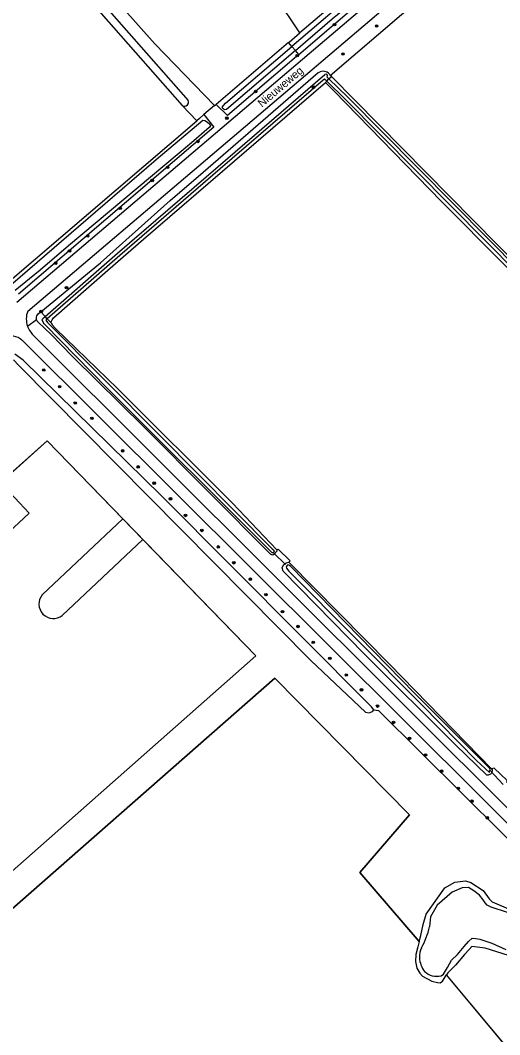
# Model space of a CAD drawing. Extents: x 141000 to 143000, y 400580 to 403500.
# Drawn here: x 141460.4 to 141610, y 402328.5 to 402645.4 of the extents above; entities that cross this region are included whole.
import ezdxf

# ---------------------------------------------------------------- set-up
doc = ezdxf.new("R2010")
doc.units = 0
for name, color, linetype in [('gg-afsc-hekwerk', 7, 'Continuous'), ('gg-anno-openbare ruimte label', 7, 'Continuous'), ('gg-knt-bronhoudergrens', 7, 'Continuous'), ('gg-knt-verharding', 7, 'Continuous'), ('gg-kntw-bovenkant insteek waterloop', 7, 'Continuous'), ('gg-kntw-waterlijn', 7, 'Continuous'), ('gg-kwrk-duiker nz buis', 7, 'Continuous'), ('gt-grn-groengrens', 7, 'Continuous'), ('gt-grn-vlakafsluiter', 7, 'Continuous'), ('gt-symb-boom', 7, 'Continuous'), ('gx-grn-maaiveld', 7, 'Continuous')]:
    doc.layers.add(name, color=color, linetype=linetype)

# ---------------------------------------------------------------- blocks, each defined once
blk = doc.blocks.new('gt0-BOOM')
at = {"layer": 'gt-symb-boom'}
for radius in [0.4, 0.2]:
    blk.add_circle((0, 0), radius, dxfattribs=at)

msp = doc.modelspace()

# ---------------------------------------------------------------- linework, layer by layer
at = {"layer": 'gg-afsc-hekwerk'}
msp.add_line((141619.05, 402316.54), (141593.45, 402347.23), dxfattribs=at)
for points in [[(141391.61, 402482.73), (141409.84, 402461.09), (141468.74, 402514.04), (141533.84, 402446.84), (141434.41, 402358.97)], [(141584.92, 402357.7), (141566.39, 402379.2), (141581.84, 402397.23), (141539.83, 402439.9), (141439.73, 402351.99)]]:
    msp.add_lwpolyline(points, dxfattribs=at)
at = {"layer": 'gg-knt-bronhoudergrens'}
for p, q in [((141510.9, 402618.77), (141515.42, 402614.02)), ((141467.21, 402465.95), (141492.38, 402489.64)), ((141498.64, 402483.18), (141473.47, 402459.49))]:
    msp.add_line(p, q, dxfattribs=at)
for points in [[(141521.02, 402618.74), (141502.4, 402638.08), (141487.01, 402655.3), (141427.04, 402727.42)], [(141557.11, 402628.18), (141608.82, 402672.5), (141656.05, 402713.39)], [(141492.38, 402489.64), (141468.74, 402514.04), (141454.22, 402500.98)], [(141454.22, 402500.98), (141463.12, 402491.43), (141413.75, 402445.4), (141384.54, 402476.72)], [(141434.41, 402358.97), (141533.84, 402446.84), (141498.64, 402483.18)], [(141540.42, 402480.02), (141540.91, 402480.22), (141544.58, 402476.53), (141544.15, 402476.12)], [(141439.73, 402351.99), (141539.83, 402439.9), (141581.84, 402397.23), (141566.39, 402379.2), (141584.92, 402357.7)], [(141612.29, 402407.3), (141612.31, 402407.96), (141608.33, 402411.82), (141607.45, 402411.59)], [(141619.64, 402315.72), (141619.64, 402315.83), (141619.05, 402316.54), (141593.45, 402347.23)]]:
    msp.add_lwpolyline(points, dxfattribs=at)
msp.add_arc((141470.69, 402463.06), 4.52, 140.2654, 307.915, dxfattribs=at)
at = {"layer": 'gg-knt-verharding'}
for p, q in [((141462.66, 402554.52), (141652.94, 402716.56)), ((141670.23, 402341.6), (141464.11, 402547.4))]:
    msp.add_line(p, q, dxfattribs=at)
for points in [[(141459.24, 402557.32), (141548.5, 402633.27), (141649.58, 402719.27), (141645.3, 402724.86)], [(141460.89, 402545.45), (141652.48, 402354.64), (141667.93, 402339.26)]]:
    msp.add_lwpolyline(points, dxfattribs=at)
for centre, radius, start, end in [((141469.02, 402552.11), 6.8, 159.2203, 199.7829), ((141469.02, 402552.11), 6.81, 199.8205, 223.8083), ((141457.83, 402542.37), 4.34, 45.2233, 122.9976)]:
    msp.add_arc(centre, radius, start, end, dxfattribs=at)
at = {"layer": 'gg-kntw-bovenkant insteek waterloop'}
for p, q in [((141564, 402655.43), (141547.64, 402641.46)), ((141544.27, 402638.59), (141547.64, 402641.46)), ((141544.12, 402638.46), (141521.47, 402619.12)), ((141557.47, 402627.82), (141557.11, 402628.18)), ((141456.44, 402563.52), (141515.42, 402614.02))]:
    msp.add_line(p, q, dxfattribs=at)
for points in [[(141417.72, 402724.06), (141436, 402703.38), (141474.9, 402659.83), (141510.9, 402618.77)], [(141422.62, 402725.57), (141421.61, 402724.68), (141421.48, 402724.13), (141421.62, 402723.85), (141512.74, 402620.3)], [(141547.27, 402634.72), (141647.53, 402720.58), (141644.78, 402724.41)], [(141547.27, 402634.72), (141525.06, 402615.7), (141521.47, 402619.12)], [(141466.75, 402554.32), (141485.36, 402569.62), (141507.17, 402589.13), (141517.47, 402597.91), (141553.38, 402629.06), (141553.98, 402629.29)], [(141470.06, 402550.74), (141470.01, 402551.16), (141470.33, 402551.86), (141470.76, 402552.41), (141487.67, 402567.37), (141498.78, 402577.04), (141555.61, 402625.98)], [(141555.61, 402625.98), (141558.2, 402623.41), (141591.86, 402588.8), (141630.63, 402549.74), (141682.01, 402497.77), (141754.99, 402423.77)], [(141557.47, 402627.82), (141609.16, 402575.48), (141658.72, 402525.06), (141659.52, 402524.25), (141660.27, 402523.5)], [(141517.67, 402615.95), (141520.77, 402612.04), (141459.83, 402559.88)], [(141517.67, 402615.95), (141516.27, 402614.75), (141515.42, 402614.02)], [(141465.37, 402551.97), (141465.37, 402552.69), (141465.56, 402553.1), (141466.07, 402553.76), (141466.75, 402554.32)], [(141540.42, 402480.02), (141540.42, 402479.53), (141539.6, 402478.61), (141539.18, 402478.34), (141538.62, 402478.57), (141519.08, 402498.08), (141498.98, 402518.33), (141476.76, 402540.31), (141469.79, 402547.41), (141468.19, 402548.96), (141465.64, 402551.43), (141465.37, 402551.97)], [(141470.06, 402550.74), (141470.3, 402550.25), (141471.37, 402549.17), (141490.74, 402530.34), (141526.62, 402494.53), (141540.42, 402480.02)], [(141570.71, 402430.04), (141569.95, 402430.92), (141504.41, 402496.87), (141461.23, 402539.23), (141458.68, 402541.09)], [(141458.24, 402539.29), (141459.94, 402537.59), (141551.04, 402445.46), (141568.13, 402429.26), (141569.27, 402429.04), (141570.3, 402429.5), (141570.71, 402430.04)], [(141607.45, 402411.59), (141607.65, 402411.23), (141607.69, 402410.82), (141607.51, 402410.27), (141607.2, 402409.94), (141606.43, 402409.57), (141606.01, 402409.57), (141596.23, 402419.09), (141567.86, 402447.43), (141542.43, 402473.35), (141542.08, 402474.32), (141542.48, 402475.28), (141543.41, 402475.96), (141544.15, 402476.12)], [(141607.45, 402411.59), (141575.6, 402444.29), (141544.15, 402476.12)], [(141584.92, 402357.7), (141585.44, 402359.5), (141586.09, 402363.01), (141587.1, 402366.14), (141592.85, 402374.37), (141595.98, 402376.14), (141599.4, 402376.56), (141601.06, 402376.04), (141604.87, 402373.56), (141606.77, 402371.02), (141607.7, 402370.03), (141614.93, 402366.9)], [(141584.92, 402357.7), (141584.42, 402355.97), (141583.86, 402353.56), (141583.75, 402351.37), (141584.11, 402349.34), (141585.04, 402347.8), (141585.95, 402346.84), (141588.87, 402345.31), (141590.61, 402344.8), (141591.43, 402344.77), (141592.16, 402345.22), (141593.45, 402347.23)], [(141612.79, 402353.23), (141605.49, 402355.58), (141601.37, 402356.08), (141600.45, 402355.18), (141599.08, 402353.54), (141596.21, 402350.3), (141593.87, 402347.88), (141593.45, 402347.23)]]:
    msp.add_lwpolyline(points, dxfattribs=at)
for centre, radius, start, end in [((141554.93, 402627.01), 2.47, 28.2363, 112.6903), ((141511.62, 402619.78), 1.24, 318.8258, 25.1412), ((141511.62, 402619.78), 1.24, 234.4403, 318.8708)]:
    msp.add_arc(centre, radius, start, end, dxfattribs=at)
at = {"layer": 'gg-kntw-waterlijn'}
msp.add_line((141556.13, 402627.68), (141556.73, 402627.09), dxfattribs=at)
for points in [[(141546.27, 402635.91), (141549.43, 402638.62), (141558.46, 402646.44), (141558.78, 402646.65), (141578.21, 402663.37), (141614.44, 402694.41), (141645.16, 402720.43), (141645.47, 402720.96), (141645.37, 402721.27), (141644.6, 402722.1), (141644.15, 402722.28), (141643.93, 402722.18), (141639.11, 402717.76), (141610.94, 402693.4), (141598.5, 402682.9), (141574.72, 402662.38), (141566.91, 402655.8), (141545.17, 402637.22)], [(141546.27, 402635.91), (141524.76, 402617.51), (141524.13, 402617.41), (141523.67, 402617.84), (141523.42, 402618.25), (141523.79, 402618.76), (141524.47, 402619.53), (141545.17, 402637.22)], [(141468.07, 402552.89), (141490.74, 402572.7), (141522.15, 402599.71), (141555.48, 402628.44)], [(141556.03, 402626.39), (141555.38, 402627.03), (141554.94, 402626.65), (141522.8, 402598.95), (141491.4, 402571.94), (141468.75, 402552.16)], [(141556.03, 402626.39), (141561.76, 402620.74), (141605.71, 402576.41), (141653.14, 402528.44), (141659.67, 402521.45), (141704.17, 402476.92), (141755.64, 402424.51)], [(141556.73, 402627.09), (141562.46, 402621.45), (141606.42, 402577.12), (141653.86, 402529.13), (141658.64, 402523.92), (141660.38, 402522.15), (141704.88, 402477.63), (141756.35, 402425.21)], [(141457.28, 402562.62), (141502.74, 402601.89), (141517.32, 402614.15), (141518.02, 402614.14), (141518.81, 402613.55), (141519.52, 402612.92), (141519.75, 402612.43), (141519.34, 402611.89), (141513.77, 402607.14), (141475.38, 402574.9), (141466.51, 402567.38), (141458.76, 402561.02)], [(141468.75, 402552.16), (141468.3, 402551.77), (141468.87, 402550.95), (141503.96, 402515.7), (141539, 402480.34), (141539.55, 402479.86), (141539.61, 402479.52), (141539.51, 402479.32), (141539.32, 402479.07), (141538.99, 402479.08), (141538.53, 402479.48), (141487.46, 402530.51), (141468.1, 402550.3), (141467.85, 402550.6), (141467.46, 402551.14), (141467.21, 402551.88), (141467.38, 402552.29), (141468.07, 402552.89)], [(141602.74, 402414.23), (141606.85, 402410.45), (141606.84, 402410.8), (141607.04, 402411.28), (141606.9, 402411.67), (141583.57, 402435.16), (141544.7, 402474.91), (141544.22, 402475.24), (141543.87, 402475.31), (141543.53, 402475.04), (141543.37, 402474.65), (141543.49, 402474.28), (141544.15, 402473.37), (141585.74, 402431.61), (141602.74, 402414.23)], [(141612.49, 402366.75), (141607.38, 402368.39), (141606.1, 402369.05), (141605.52, 402369.68), (141604.9, 402370.68), (141603.72, 402372.16), (141601.99, 402373.49), (141600.26, 402374.48), (141598.31, 402374.46), (141595.14, 402373.1), (141590.55, 402368.96), (141588.4, 402365.38), (141588.12, 402362.2)], [(141591.71, 402346.94), (141592.44, 402347.49), (141593.14, 402348.47), (141593.68, 402349.58), (141594.99, 402351.8), (141596.85, 402353.58), (141598.9, 402356.05), (141600.3, 402357.62), (141601.44, 402358.7), (141602.61, 402358.61), (141603.84, 402358.34), (141607.61, 402357.12), (141611.95, 402355.11)]]:
    msp.add_lwpolyline(points, dxfattribs=at)
for centre, radius, start, end in [((141555.81, 402628.06), 0.5, 310.7933, 130.7699), ((141566.03, 402367.01), 22.6, 330.0153, 347.7216), ((141592.62, 402352.7), 7.63, 156.7801, 180.5858), ((141592.57, 402352.92), 7.59, 182.2103, 217.9576), ((141590.42, 402352.56), 5.77, 228.3914, 282.9157)]:
    msp.add_arc(centre, radius, start, end, dxfattribs=at)
at = {"layer": 'gg-kwrk-duiker nz buis'}
for p, q in [((141543.13, 402475.42), (141539.53, 402478.94)), ((141607.06, 402411.05), (141611.15, 402406.64))]:
    msp.add_line(p, q, dxfattribs=at)
at = {"layer": 'gt-grn-groengrens'}
for p, q in [((141547.64, 402641.46), (141522.46, 402679.4)), ((141521.02, 402618.74), (141517.67, 402615.95)), ((141462.62, 402549.81), (141465.37, 402551.97)), ((141498.64, 402483.18), (141492.38, 402489.64))]:
    msp.add_line(p, q, dxfattribs=at)
msp.add_lwpolyline([(141570.71, 402430.04), (141572.2, 402429.79), (141598.62, 402403.58), (141622.59, 402379.86), (141650.36, 402352.52), (141665.84, 402337.11)], dxfattribs=at)
at = {"layer": 'gt-grn-vlakafsluiter'}
for p, q in [((141545.17, 402637.22), (141544.12, 402638.46)), ((141546.27, 402635.91), (141545.17, 402637.22)), ((141547.27, 402634.72), (141546.27, 402635.91)), ((141555.61, 402625.98), (141556.03, 402626.39)), ((141556.03, 402626.39), (141556.73, 402627.09)), ((141556.73, 402627.09), (141557.47, 402627.82)), ((141468.07, 402552.89), (141466.75, 402554.32)), ((141468.75, 402552.16), (141468.07, 402552.89)), ((141468.75, 402552.16), (141470.06, 402550.74))]:
    msp.add_line(p, q, dxfattribs=at)
at = {"layer": 'gx-grn-maaiveld'}
for p, q in [((141544.12, 402638.46), (141544.27, 402638.59)), ((141521.02, 402618.74), (141521.47, 402619.12))]:
    msp.add_line(p, q, dxfattribs=at)

# ---------------------------------------------------------------- block references
at = {"layer": 'gt-symb-boom'}
for p in [(141558.47, 402644.03), (141571.6, 402643.61), (141561.12, 402634.88), (141546.82, 402634.33), (141533.83, 402623.17), (141551.88, 402624.5), (141524.86, 402614.81), (141515.84, 402607.56), (141506.36, 402599.47), (141501.51, 402595.37), (141491.54, 402586.68), (141481.39, 402578.02), (141475.74, 402573.34), (141471.41, 402569.52), (141474.8, 402561.89), (141466.88, 402554.43), (141467.67, 402536.17), (141472.64, 402530.96), (141477.52, 402525.85), (141482.72, 402521.05), (141492.3, 402510.92), (141497.15, 402505.89), (141502.16, 402500.81), (141507.25, 402495.9), (141511.92, 402490.74), (141517.04, 402486.06), (141522.18, 402480.9), (141527.04, 402475.96), (141532.18, 402470.82), (141537.04, 402465.97), (141542.23, 402460.67), (141547.07, 402456.05), (141551.82, 402451.1), (141556.98, 402446.11), (141562.14, 402440.91), (141566.87, 402436.27), (141571.91, 402431.19), (141576.9, 402426.09), (141581.9, 402421.09), (141586.89, 402415.9), (141591.9, 402410.84), (141597.1, 402405.48), (141601.38, 402401.47), (141606.17, 402396.27)]:
    msp.add_blockref('gt0-BOOM', p, dxfattribs=at)

# ---------------------------------------------------------------- texts
at = {"layer": 'gg-anno-openbare ruimte label'}
msp.add_text('Nieuweweg', height=2.5, rotation=40.4, dxfattribs=at).set_placement((141535.79, 402618.1))

doc.saveas('drawing.dxf')
